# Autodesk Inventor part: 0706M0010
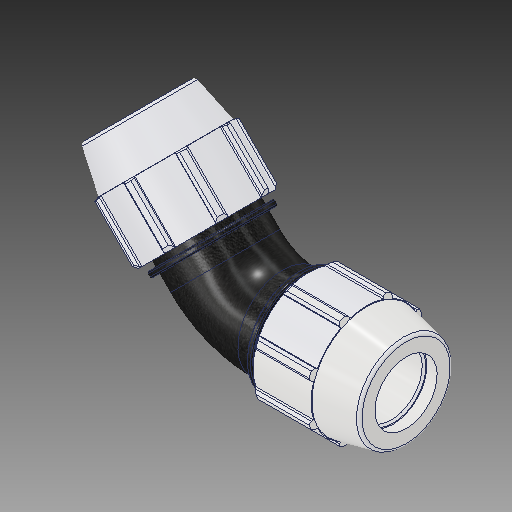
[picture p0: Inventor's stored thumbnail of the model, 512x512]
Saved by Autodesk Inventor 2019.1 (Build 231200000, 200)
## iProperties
Created: 2017-02
Part Number: 0706M0010
Material: PVC-Piping
Description: PLASSON 45° ELBOW 1'' - 1''
Document SubType Name: Modeling
Designer: KIM
Mass: 92.6774 g
Surface Area: 199.44 cm^2
Volume: 66.1981 cm^3
Density: 1.4 g/cm^3
Appearance: PTFE
Author: KIM
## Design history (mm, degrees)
derived "0706M0.ipt"
feature "Solid1::0706M0.ipt"
tag "TaggingFeature1"
body "Solid1"
other parameters: "d2" = 33.3, "d4" = 7.00617, "d5" = 21.0185, "d7" = 64.008, "d9" = 12.01057, "d11" = 2.80247, "d13" = 120 deg, "d14" = 49.95, "d15" = 12 deg, "d16" = 55.68696, "d18" = 1.665, "d19" = 35 deg, "d20" = 17.5 deg, "d21" = 59.52744, "d23" = 0, "d25" = 360 deg, "d27" = 1.28016, "d33" = 0.666, "d42" = 31.10738, "d43" = 1.92024, "d46" = 0.999, "d51" = 84.074, "d59" = 135 deg, "d63" = 66.04, "d67" = 48.006, "d68" = 2.80247, "d72" = 1.5, "d73" = 0, "d74" = 0, "d_" = 33.3, "E_" = 64.008, "A_" = 84.074, "l_" = 66.04
